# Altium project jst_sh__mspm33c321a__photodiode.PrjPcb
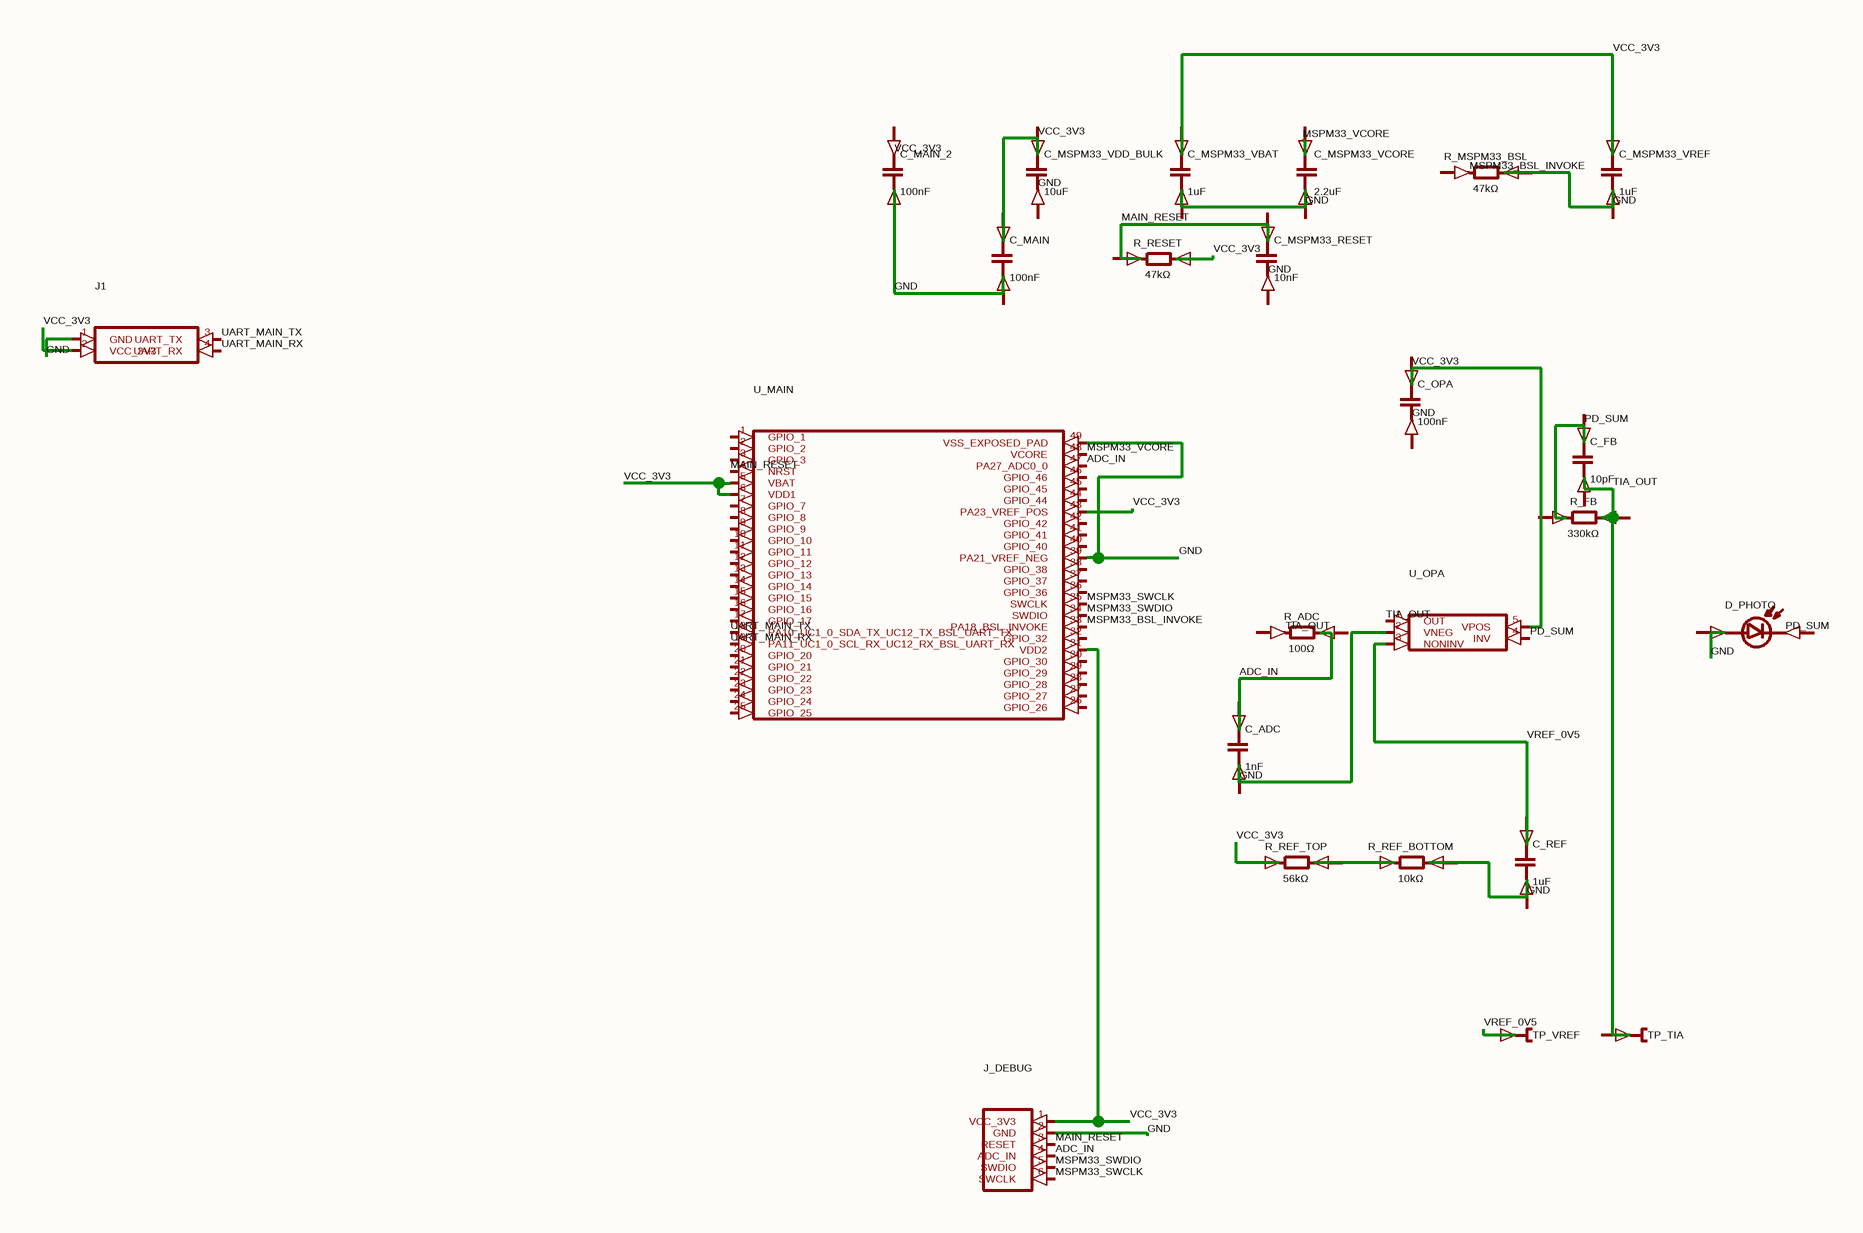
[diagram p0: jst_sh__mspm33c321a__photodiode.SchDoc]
1 sheet, 24 parts. Net scope: global (net labels, ports and power ports of the same name join across sheets).
Board file: jst_sh__mspm33c321a__photodiode.PcbDoc

## Sheet jst_sh__mspm33c321a__photodiode.SchDoc
size 207 x 150 mm

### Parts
C_ADC  1nF
C_FB  10pF
C_MAIN  100nF
C_MAIN_2  100nF
C_MSPM33_RESET  10nF
C_MSPM33_VBAT  1uF
C_MSPM33_VCORE  2.2uF
C_MSPM33_VDD_BULK  10uF
C_MSPM33_VREF  1uF
C_OPA  100nF
C_REF  1uF
D_PHOTO  (no value)
J1  (no value)
J_DEBUG  (no value)
R_ADC  100Ω
R_FB  330kΩ
R_MSPM33_BSL  47kΩ
R_REF_BOTTOM  10kΩ
R_REF_TOP  56kΩ
R_RESET  47kΩ
TP_TIA  (no value)
TP_VREF  (no value)
U_MAIN  (no value)
U_OPA  (no value)

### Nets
ADC_IN: C_ADC.1(anode) J_DEBUG.4(ADC_IN) U_MAIN.47(PA27_ADC0_0)
GND: C_MAIN_2.2(cathode) J1.1(GND) J_DEBUG.2(GND) R_MSPM33_BSL.2(cathode) R_REF_BOTTOM.2(cathode) U_MAIN.39(PA21_VREF_NEG) U_MAIN.49(VSS_EXPOSED_PAD) U_OPA.2(VNEG)
MAIN_RESET: J_DEBUG.3(RESET) U_MAIN.4(NRST)
MSPM33_BSL_INVOKE: U_MAIN.33(PA18_BSL_INVOKE)
MSPM33_SWCLK: J_DEBUG.6(SWCLK) U_MAIN.35(SWCLK)
MSPM33_SWDIO: J_DEBUG.5(SWDIO) U_MAIN.34(SWDIO)
MSPM33_VCORE: U_MAIN.48(VCORE)
PD_SUM: U_OPA.4(INV)
TIA_OUT: U_OPA.1(OUT)
UART_MAIN_RX: J1.4(UART_RX) U_MAIN.19(PA11_UC1_0_SCL_RX_UC12_RX_BSL_UART_RX)
UART_MAIN_TX: J1.3(UART_TX) U_MAIN.18(PA10_UC1_0_SDA_TX_UC12_TX_BSL_UART_TX)
VCC_3V3: C_MAIN.1(anode) C_MSPM33_VBAT.1(anode) C_MSPM33_VREF.1(anode) J1.2(VCC_3V3) J_DEBUG.1(VCC_3V3) R_REF_TOP.1(anode) R_RESET.2(cathode) U_MAIN.5(VBAT) U_MAIN.6(VDD1) U_MAIN.31(VDD2) U_MAIN.43(PA23_VREF_POS) U_OPA.5(VPOS)
VREF_0V5: C_REF.1(anode) TP_VREF.1(pin1) U_OPA.3(NONINV)
NetR_REF_BOTTOM_1: R_REF_BOTTOM.1(anode) R_REF_TOP.2(cathode)

Not connected (* = marked no-connect by the designer): C_ADC 2(cathode); C_FB 1(anode) 2(cathode); C_MAIN 2(cathode); C_MAIN_2 1(anode); C_MSPM33_RESET 1(anode) 2(cathode); C_MSPM33_VBAT 2(cathode); C_MSPM33_VCORE 1(anode) 2(cathode); C_MSPM33_VDD_BULK 1(anode) 2(cathode); C_MSPM33_VREF 2(cathode); C_OPA 1(anode) 2(cathode); C_REF 2(cathode); D_PHOTO 1(anode) 2(cathode); R_ADC 1(anode) 2(cathode); R_FB 1(anode) 2(cathode); R_MSPM33_BSL 1(anode); R_RESET 1(anode); TP_TIA 1(pin1); U_MAIN 1(GPIO_1) 2(GPIO_2) 3(GPIO_3) 7(GPIO_7) 8(GPIO_8) 9(GPIO_9) 10(GPIO_10) 11(GPIO_11) 12(GPIO_12) 13(GPIO_13) 14(GPIO_14) 15(GPIO_15) 16(GPIO_16) 17(GPIO_17) 20(GPIO_20) 21(GPIO_21) 22(GPIO_22) 23(GPIO_23) 24(GPIO_24) 25(GPIO_25) 26(GPIO_26) 27(GPIO_27) 28(GPIO_28) 29(GPIO_29) 30(GPIO_30) 32(GPIO_32) 36(GPIO_36) 37(GPIO_37) 38(GPIO_38) 40(GPIO_40) 41(GPIO_41) 42(GPIO_42) 44(GPIO_44) 45(GPIO_45) 46(GPIO_46)

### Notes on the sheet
- Labels drawn without touching a wire or pin: GND, MSPM33_BSL_INVOKE, PD_SUM, TIA_OUT, VCC_3V3

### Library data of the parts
C_ADC C_FB C_MAIN C_MAIN_2 C_MSPM33_RESET C_MSPM33_VBAT C_MSPM33_VCORE C_MSPM33_VDD_BULK C_MSPM33_VREF C_OPA C_REF = capacitor_down
D_PHOTO = photodiode_horz
J1 = J1
J_DEBUG = J_DEBUG
R_ADC R_FB R_MSPM33_BSL R_REF_BOTTOM R_REF_TOP R_RESET = boxresistor_right
TP_TIA TP_VREF = testpoint_right
U_MAIN = U_MAIN
U_OPA = U_OPA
